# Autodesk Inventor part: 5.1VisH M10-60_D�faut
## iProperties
Created: 2011-01
Part Number: 5.1VisH M10-60_D�faut
Document SubType Name: Modeling
Designer: eric
Density: 1 g/cm^3
Mass: 6.11218 g
Surface Area: 26.5299 cm^2
Volume: 6.11218 cm^3
Author: eric
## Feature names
1. Base1
